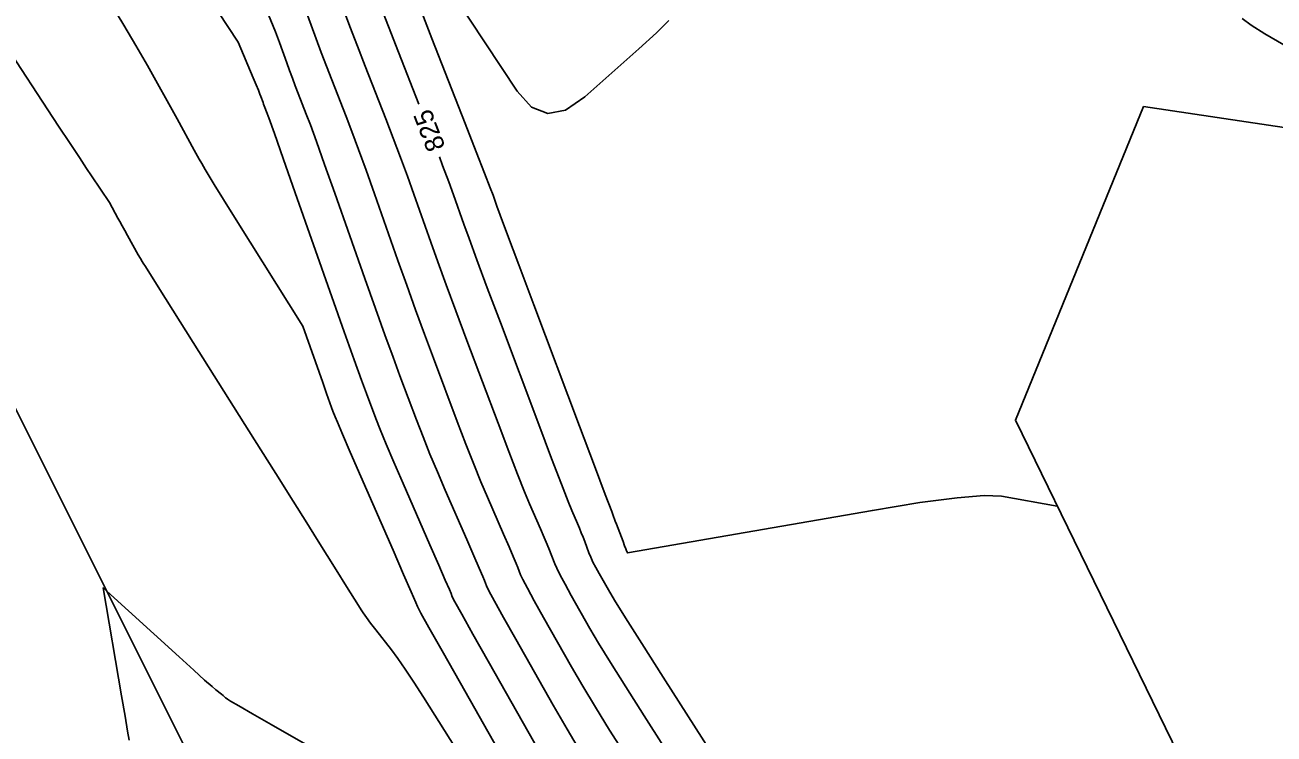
# Model space of a CAD drawing. Extents: x 1715724 to 1716561, y 394063 to 395906.
# Drawn here: x 1716279.5 to 1716371.9, y 394602.7 to 394655.2 of the extents above; entities that cross this region are included whole.
import ezdxf

# ---------------------------------------------------------------- set-up
doc = ezdxf.new("R2010")
doc.units = 0
for name, color, linetype in [('DT_X_Contour_Major', 7, 'Continuous'), ('DT_X_Contour_Minor', 7, 'Continuous'), ('DT_X_TIN_Hull', 7, 'Continuous'), ('GE_P_CL_10', 7, 'Continuous')]:
    doc.layers.add(name, color=color, linetype=linetype)

msp = doc.modelspace()

# ---------------------------------------------------------------- linework, layer by layer
at = {"layer": 'DT_X_Contour_Major'}
for points in [[(1716305.665, 394657.034), (1716306.39, 394655.126), (1716307.131, 394653.217), (1716308.634, 394649.389)], [(1716285.881, 394656.729), (1716286.812, 394655.225), (1716287.701, 394653.729), (1716288.546, 394652.242), (1716290.741, 394648.286), (1716292.022, 394645.976), (1716292.389, 394645.315), (1716292.574, 394644.982), (1716292.823, 394644.533), (1716293.037, 394644.175), (1716293.492, 394643.436), (1716294.188, 394642.317), (1716295.126, 394640.819), (1716300.062, 394632.936), (1716301.529, 394628.771), (1716301.812, 394627.97), (1716302.187, 394626.914), (1716302.28, 394626.66), (1716302.444, 394626.225), (1716302.609, 394625.827), (1716302.983, 394624.959), (1716303.564, 394623.62), (1716304.353, 394621.812), (1716306.734, 394616.363), (1716307.517, 394614.569), (1716308.081, 394613.277), (1716308.425, 394612.484), (1716308.551, 394612.193), (1716308.592, 394612.081), (1716308.8, 394611.702), (1716309.392, 394610.647), (1716310.369, 394608.916), (1716311.729, 394606.51), (1716315.871, 394599.191)], [(1716310.159, 394645.475), (1716310.399, 394644.85), (1716310.86, 394643.624), (1716311.205, 394642.671), (1716311.972, 394640.495), (1716312.356, 394639.427), (1716312.935, 394637.856), (1716313.709, 394635.781), (1716314.677, 394633.203), (1716317.518, 394625.657), (1716318.469, 394623.137), (1716319.194, 394621.235), (1716319.69, 394619.951), (1716319.96, 394619.285), (1716320.376, 394618.334), (1716320.526, 394617.983), (1716320.667, 394617.644), (1716320.798, 394617.316), (1716320.919, 394617.001), (1716321.227, 394616.174), (1716321.361, 394615.846), (1716321.531, 394615.48), (1716321.736, 394615.077), (1716321.978, 394614.638), (1716322.67, 394613.415), (1716323.118, 394612.668), (1716323.943, 394611.344), (1716325.146, 394609.442), (1716326.726, 394606.964), (1716331.443, 394599.586)]]:
    msp.add_lwpolyline(points, dxfattribs=at)
at = {"layer": 'DT_X_Contour_Minor'}
for points in [[(1716288.685, 394663.982), (1716295.271, 394653.963), (1716296.385, 394651.322), (1716296.6, 394650.811), (1716296.765, 394650.412), (1716296.882, 394650.125), (1716296.949, 394649.949), (1716297.109, 394649.506), (1716297.153, 394649.386), (1716297.199, 394649.265), (1716297.246, 394649.144), (1716297.373, 394648.822), (1716297.541, 394648.356), (1716297.952, 394647.199), (1716298.604, 394645.352), (1716299.498, 394642.814), (1716302.205, 394635.127), (1716303.126, 394632.517), (1716303.859, 394630.454), (1716304.403, 394628.938), (1716304.76, 394627.968), (1716305.459, 394626.111), (1716305.781, 394625.289), (1716306.225, 394624.214), (1716306.789, 394622.886), (1716307.474, 394621.306), (1716309.462, 394616.757), (1716310.119, 394615.252), (1716310.598, 394614.15), (1716310.9, 394613.451), (1716311.024, 394613.154), (1716311.119, 394612.9), (1716311.312, 394612.531), (1716311.82, 394611.614), (1716312.642, 394610.148), (1716313.779, 394608.135), (1716317.231, 394602.036)], [(1716299.696, 394657.938), (1716300.665, 394655.237), (1716301.033, 394654.224), (1716301.409, 394653.21), (1716301.795, 394652.195), (1716302.189, 394651.18), (1716303.252, 394648.472), (1716303.682, 394647.353), (1716304.175, 394646.025), (1716304.732, 394644.488), (1716305.352, 394642.743), (1716307.088, 394637.811), (1716307.741, 394635.972), (1716308.397, 394634.155), (1716309.056, 394632.36), (1716309.718, 394630.586), (1716311.488, 394625.884), (1716312.125, 394624.213), (1716312.709, 394622.724), (1716313.24, 394621.418), (1716313.717, 394620.296), (1716314.919, 394617.545), (1716315.323, 394616.617), (1716315.633, 394615.897), (1716315.849, 394615.383), (1716315.972, 394615.077), (1716316.173, 394614.537), (1716316.337, 394614.188), (1716316.675, 394613.547), (1716317.189, 394612.613), (1716317.878, 394611.386), (1716319.95, 394607.725), (1716320.78, 394606.29), (1716321.715, 394604.728), (1716322.756, 394603.042), (1716323.902, 394601.229)], [(1716311.178, 394657.534), (1716315.911, 394650.33), (1716316.985, 394649.146), (1716318.18, 394648.681), (1716319.496, 394648.937), (1716320.933, 394649.911), (1716324.925, 394653.471), (1716326.23, 394654.663), (1716327.151, 394655.572)], [(1716302.995, 394656.582), (1716303.537, 394655.122), (1716304.092, 394653.661), (1716304.66, 394652.198), (1716306.191, 394648.298), (1716306.752, 394646.851), (1716307.287, 394645.437), (1716307.796, 394644.056), (1716308.278, 394642.707), (1716309.53, 394639.153), (1716310.049, 394637.699), (1716310.666, 394636.005), (1716311.383, 394634.07), (1716312.198, 394631.894), (1716314.503, 394625.771), (1716315.297, 394623.675), (1716315.951, 394621.979), (1716316.465, 394620.684), (1716316.839, 394619.79), (1716317.647, 394617.939), (1716317.925, 394617.3), (1716318.15, 394616.77), (1716318.324, 394616.35), (1716318.445, 394616.039), (1716318.7, 394615.356), (1716318.849, 394615.017), (1716319.103, 394614.514), (1716319.463, 394613.845), (1716319.928, 394613.012), (1716321.31, 394610.57), (1716321.949, 394609.479), (1716322.829, 394608.036), (1716323.951, 394606.242), (1716325.314, 394604.097), (1716329.271, 394597.907)], [(1716308.728, 394656.479), (1716309.603, 394654.235), (1716312.07, 394647.949), (1716312.893, 394645.849), (1716313.511, 394644.263), (1716313.924, 394643.192), (1716314.132, 394642.635), (1716314.413, 394641.837), (1716314.664, 394641.154), (1716315.204, 394639.706), (1716316.035, 394637.492), (1716317.156, 394634.512), (1716320.532, 394625.544), (1716321.641, 394622.599), (1716322.436, 394620.49), (1716322.916, 394619.217), (1716323.081, 394618.779), (1716323.104, 394618.728), (1716323.128, 394618.665), (1716323.185, 394618.517), (1716323.273, 394618.283), (1716323.392, 394617.962), (1716323.754, 394616.993), (1716323.873, 394616.675), (1716323.958, 394616.447), (1716324.01, 394616.31), (1716324.027, 394616.263), (1716324.029, 394616.259), (1716324.031, 394616.256), (1716324.035, 394616.25), (1716324.041, 394616.24), (1716324.05, 394616.227), (1716324.093, 394616.159), (1716342.217, 394619.309), (1716345.726, 394619.88), (1716348.486, 394620.244), (1716350.497, 394620.4), (1716351.759, 394620.35), (1716355.901, 394619.629)], [(1716297.515, 394655.985), (1716298.019, 394654.737), (1716298.322, 394653.943), (1716298.865, 394652.432), (1716299.071, 394651.865), (1716299.281, 394651.298), (1716299.497, 394650.73), (1716299.718, 394650.162), (1716300.312, 394648.647), (1716300.612, 394647.854), (1716301.063, 394646.612), (1716301.668, 394644.92), (1716302.425, 394642.778), (1716304.647, 394636.469), (1716305.434, 394634.245), (1716306.128, 394632.305), (1716306.73, 394630.649), (1716307.239, 394629.277), (1716308.474, 394625.998), (1716308.953, 394624.751), (1716309.467, 394623.469), (1716310.014, 394622.152), (1716310.596, 394620.801), (1716312.191, 394617.151), (1716312.721, 394615.935), (1716313.115, 394615.023), (1716313.374, 394614.417), (1716313.498, 394614.116), (1716313.646, 394613.719), (1716313.824, 394613.36), (1716314.247, 394612.58), (1716314.916, 394611.381), (1716315.829, 394609.761), (1716318.591, 394604.881), (1716319.611, 394603.101), (1716320.601, 394601.421)], [(1716369.587, 394655.729), (1716370.241, 394655.236), (1716371.269, 394654.58), (1716372.672, 394653.762)], [(1716277.621, 394654.372), (1716281.977, 394647.76), (1716282.829, 394646.467), (1716283.519, 394645.422), (1716284.046, 394644.625), (1716284.411, 394644.076), (1716285.734, 394642.093), (1716286.371, 394640.945), (1716286.518, 394640.68), (1716286.686, 394640.377), (1716286.876, 394640.035), (1716287.087, 394639.655), (1716287.878, 394638.23), (1716288.039, 394637.945), (1716288.159, 394637.737), (1716288.239, 394637.604), (1716288.397, 394637.351), (1716289.34, 394635.854), (1716290.43, 394634.126), (1716291.932, 394631.744), (1716296.487, 394624.521), (1716298.055, 394622.033), (1716299.342, 394619.987), (1716300.349, 394618.383), (1716301.075, 394617.221), (1716302.638, 394614.712), (1716303.166, 394613.865), (1716303.576, 394613.205), (1716303.871, 394612.734), (1716304.048, 394612.45), (1716304.366, 394611.945), (1716304.525, 394611.709), (1716304.761, 394611.384), (1716305.074, 394610.967), (1716305.466, 394610.459), (1716306.614, 394608.985), (1716307.085, 394608.351), (1716307.638, 394607.555), (1716308.272, 394606.597), (1716308.987, 394605.477), (1716312.517, 394599.871)], [(1716305.1, 394599.233), (1716297.709, 394603.453), (1716296.32, 394604.249), (1716295.317, 394604.825), (1716294.703, 394605.182), (1716294.477, 394605.321), (1716294.39, 394605.399), (1716294.342, 394605.44), (1716294.265, 394605.503), (1716294.158, 394605.589), (1716294.022, 394605.697), (1716293.618, 394606.017), (1716293.335, 394606.259), (1716292.788, 394606.746), (1716291.978, 394607.477), (1716290.904, 394608.452), (1716285.276, 394613.576), (1716286.643, 394605.569), (1716286.901, 394604.061), (1716287.087, 394602.971), (1716287.202, 394602.299)]]:
    msp.add_lwpolyline(points, dxfattribs=at)
at = {"layer": 'DT_X_TIN_Hull'}
msp.add_lwpolyline([(1716375.711, 394577.402), (1716364.4, 394602.185), (1716352.803, 394625.988), (1716362.292, 394649.196), (1716385.754, 394645.713)], dxfattribs=at)
at = {"layer": 'GE_P_CL_10'}
msp.add_line((1716447.809, 394289.082), (1716249.46, 394685.42), dxfattribs=at)

# ---------------------------------------------------------------- texts
at = {"layer": 'DT_X_Contour_Major'}
msp.add_text('825', height=1.4, rotation=111.28896, dxfattribs=at).set_placement((1716310.627, 394646.214))

doc.saveas('drawing.dxf')
